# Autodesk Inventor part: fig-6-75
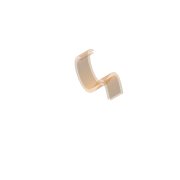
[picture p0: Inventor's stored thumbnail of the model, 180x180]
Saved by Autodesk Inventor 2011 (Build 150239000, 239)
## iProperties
Shininess: 64.0
Length Units: 11269
Angle Units: 11279
Time Units: 11290
Mass Units: 11283
Length Display Precision: 3
Angle Display Precision: 2
Compacted: True
Part Number: fig-6-75
Document SubType Name: Modeling
Created: 2002-12
Designer: deepak
Density: 1 g/cm^3
Density: 0.0
Volumn: 0.0
Area: 0.0
PropertySet Name: Model Information
Control State: 0
Master: False
Checked Out: False
Author: deepak
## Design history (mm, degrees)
sketch "Sketch1"
  geometry: 5 further points
  constraints: 5 other
extrude_surface "ExtrusionSrf1" sketch "Sketch1" dims "d0" = 20, "d1" = 0
feature "OffsetSrf2" dims "d8" = 4, "d9" = 4
body "Solid1"
body "Srf1"
body "Srf2"
